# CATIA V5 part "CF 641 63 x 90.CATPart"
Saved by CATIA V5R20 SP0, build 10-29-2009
Part number: CF 641 63 x 90
Definition: NONE
Nomenclature: CF 641 63 x 90
Source: Unknown
Description: CF 641 63 x 90
Bounding box of the stored display mesh (mm): x -42 to 48, y -46 to 46, z -46 to 46
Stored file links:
  C:\Users\Utente\Desktop\IO LAVORO\3D X SITO CF\X SITO\CF 641\CF 641 63 x 90.CATPart
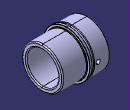
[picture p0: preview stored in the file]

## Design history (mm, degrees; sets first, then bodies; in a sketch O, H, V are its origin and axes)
Body1 "CF 641 63 x 90" (main body)
  Solid1: solid without history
